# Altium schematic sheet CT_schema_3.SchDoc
size 422 x 246 mm
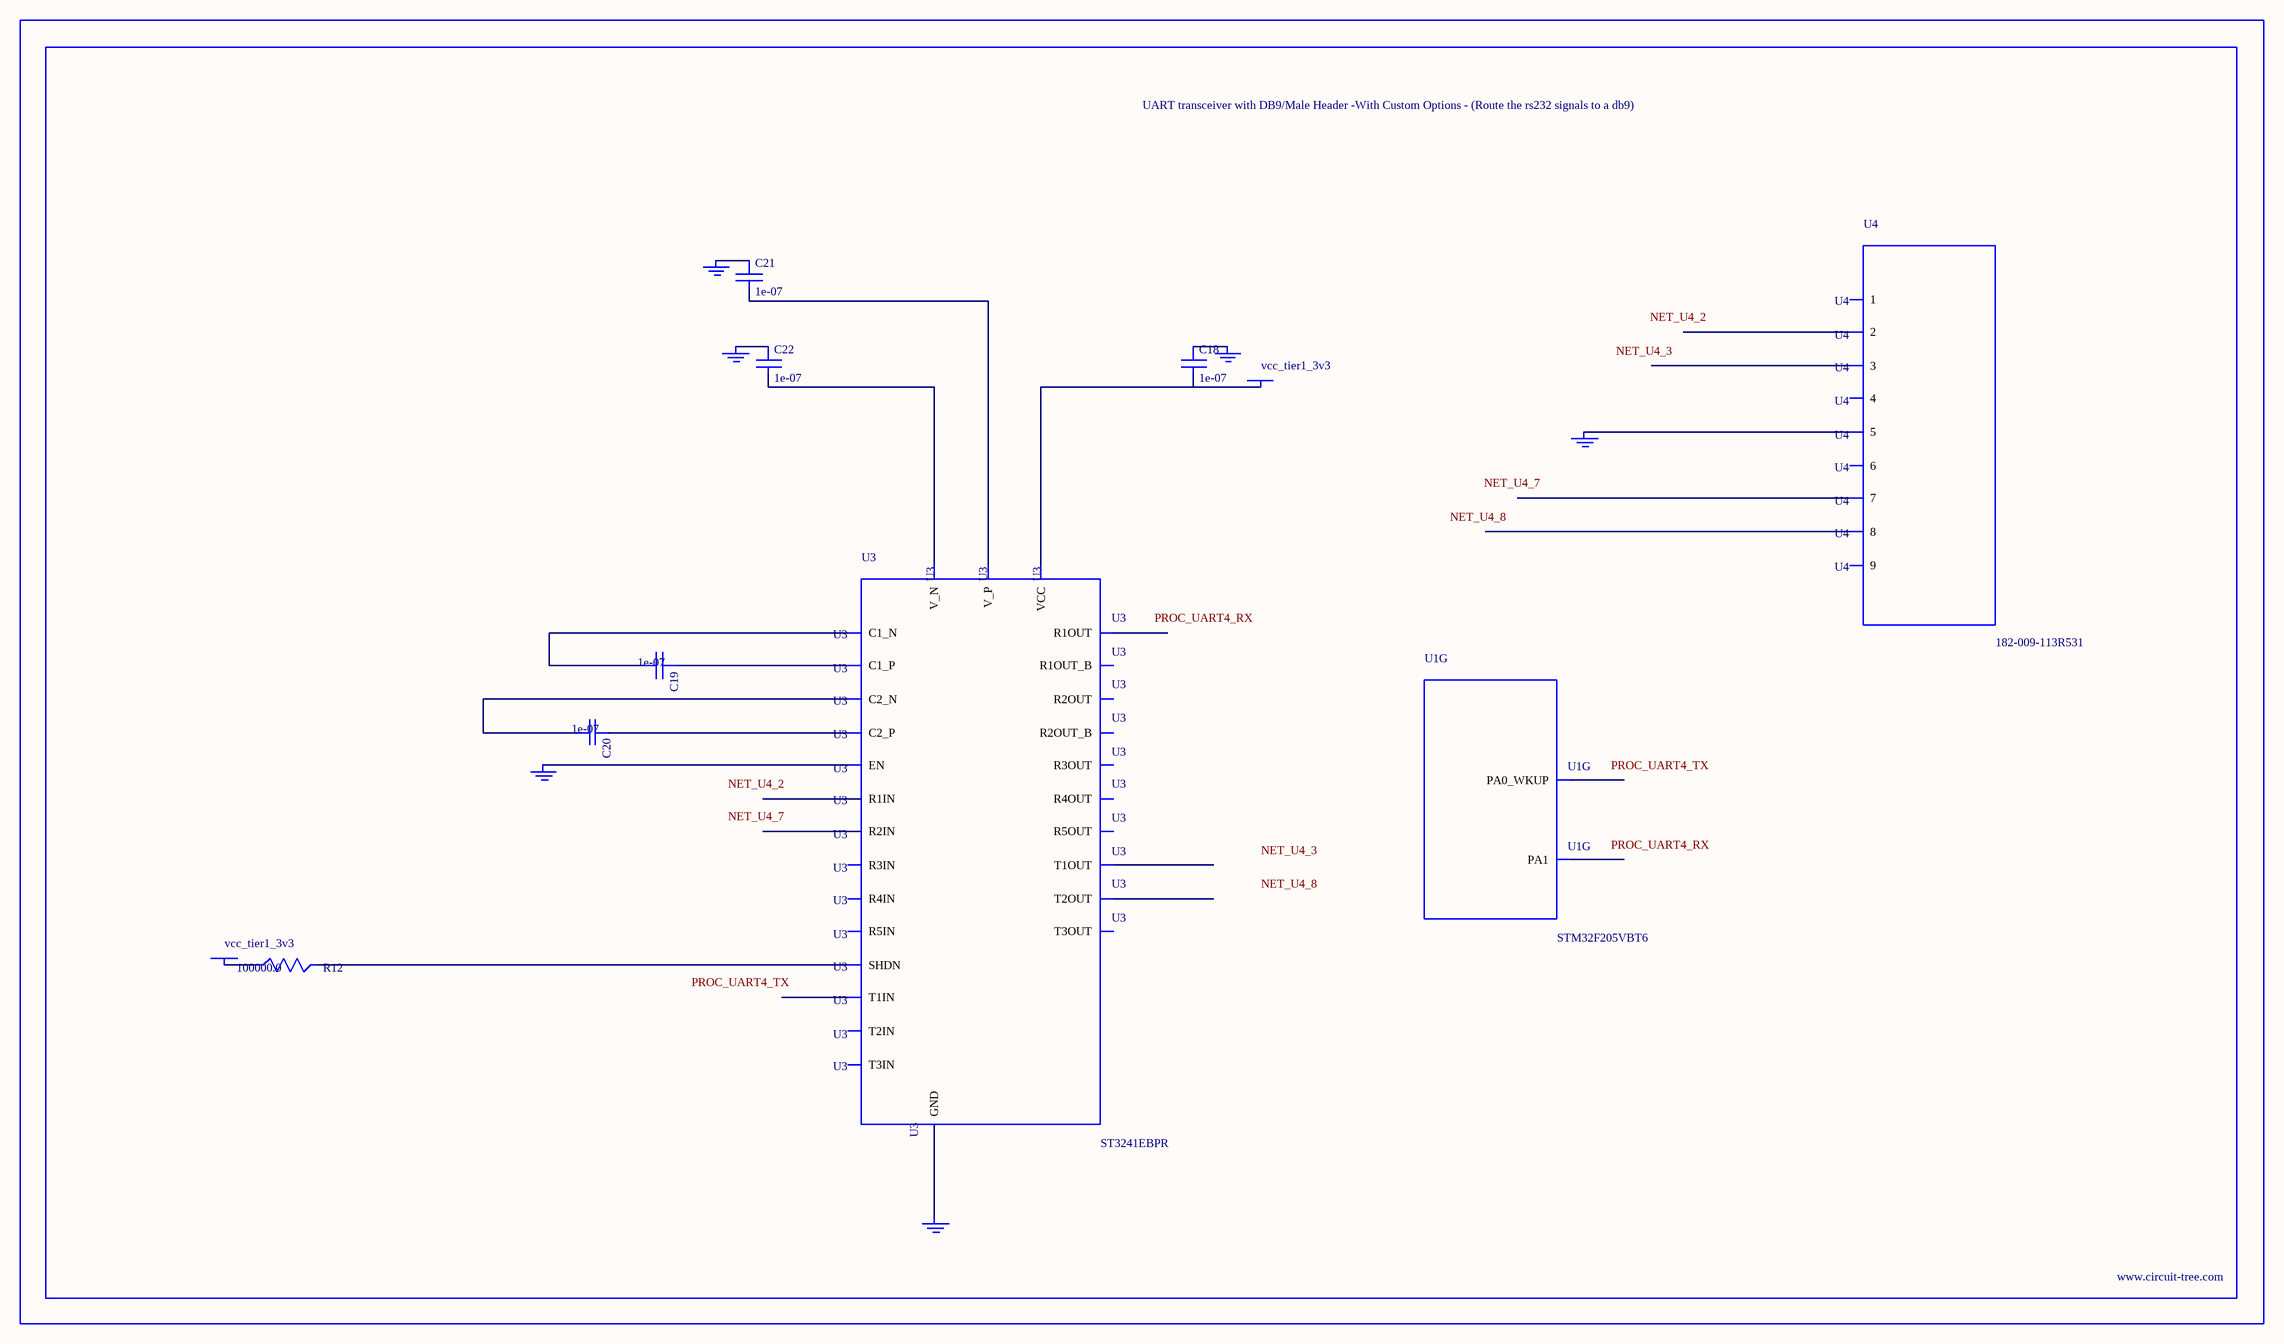
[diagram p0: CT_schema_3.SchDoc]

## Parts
BORDER2  (no value)
C18  1e-07  [C0402]
C19  1e-07  [C0402]
C20  1e-07  [C0402]
C21  1e-07  [C0402]
C22  1e-07  [C0402]
GND_INSTANCE_2_0  (no value)
GND_INSTANCE_2_1  (no value)
GND_INSTANCE_2_2  (no value)
GND_INSTANCE_2_3  (no value)
GND_INSTANCE_2_4  (no value)
GND_INSTANCE_2_5  (no value)
POWER_INSTANCE_2_0  vcc_tier1_3v3
POWER_INSTANCE_2_1  vcc_tier1_3v3
R12  100000.0  [R0603]
U1  STM32F205VBT6  [LQFP100]  (part G of 8)
U3  ST3241EBPR  [SSOP-28]
U4  182-009-113R531  [182-009-MALE]

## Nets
NetC18_1: C18.1 GND_INSTANCE_2_2.0(GND)
NetC18_2: C18.2 POWER_INSTANCE_2_1.0(PWR) U3.26(VCC)
NetC19_1: C19.1 U3.28(C1_P)
NetC19_2: C19.2 U3.24(C1_N)
NetC20_1: C20.1 U3.1(C2_P)
NetC20_2: C20.2 U3.2(C2_N)
NetC21_1: C21.1 GND_INSTANCE_2_3.0(GND)
NetC21_2: C21.2 U3.27(V_P)
NetC22_1: C22.1 GND_INSTANCE_2_0.0(GND)
NetC22_2: C22.2 U3.3(V_N)
NetGND_INSTANCE_2_1_0: GND_INSTANCE_2_1.0(GND) U3.23(EN)
NetGND_INSTANCE_2_4_0: GND_INSTANCE_2_4.0(GND) U3.25(GND)
NetGND_INSTANCE_2_5_0: GND_INSTANCE_2_5.0(GND) U4.5
NetPOWER_INSTANCE_2_0_0: POWER_INSTANCE_2_0.0(PWR) R12.1
NetR12_2: R12.2 U3.22(SHDN)

Not connected (* = marked no-connect by the designer): U1 23(PA0_WKUP) 24(PA1); U3 4(R1IN) 5(R2IN) 6(R3IN) 7(R4IN) 8(R5IN) 9(T1OUT) 10(T2OUT) 11(T3OUT) 12(T3IN) 13(T2IN) 14(T1IN) 15(R5OUT) 16(R4OUT) 17(R3OUT) 18(R2OUT) 19(R1OUT) 20(R2OUT_B) 21(R1OUT_B); U4 1 2 3 4 6 7 8 9

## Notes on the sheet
- Labels drawn without touching a wire or pin: NET_U4_2, NET_U4_3, NET_U4_7, NET_U4_8, PROC_UART4_RX, PROC_UART4_TX

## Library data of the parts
BORDER2 = BORDER_PAGE2
C18-C22 = C0402C104K3RACTU
GND_INSTANCE_2_0-GND_INSTANCE_2_5 = GND
POWER_INSTANCE_2_0 POWER_INSTANCE_2_1 = PWR
R12 = RC0603JR-07100KL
